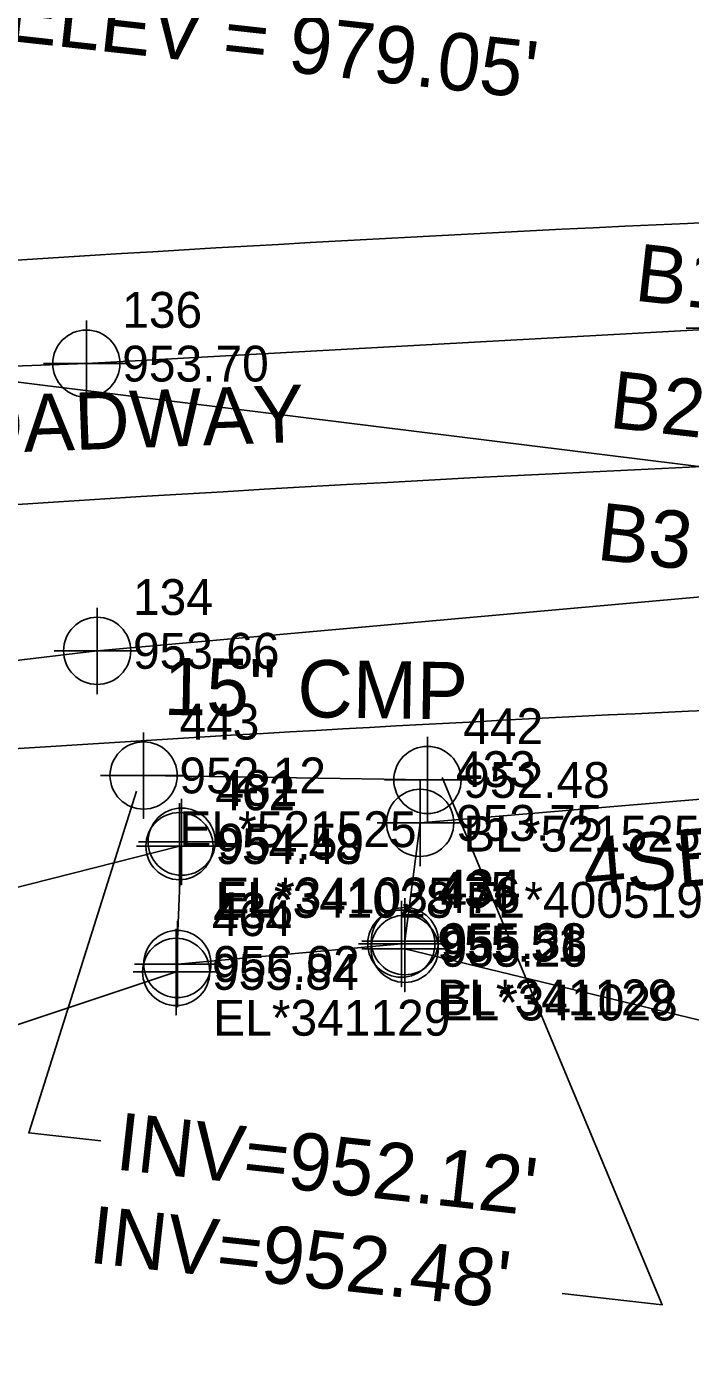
# Model space of a CAD drawing. Extents: x 1150279 to 1151282, y 655434 to 657999.
# Drawn here: x 1150667.5 to 1150713.8, y 657070.4 to 657163.6 of the extents above; entities that cross this region are included whole.
import ezdxf

# ---------------------------------------------------------------- set-up
doc = ezdxf.new("R2010")
doc.units = 0
for name, color, linetype in [('COGO Default Chain', 7, 'Continuous'), ('COGO Default Curve', 7, 'Continuous'), ('Exist Horizontal Alignment', 7, 'Continuous'), ('Exist Other Culture Fence Line', 7, 'Continuous'), ('Exist Other Culture Fence Line Cogo Comment', 7, 'Continuous'), ('Exist Other Culture Fence Line Cogo Elevation', 7, 'Continuous'), ('Exist Other Culture Fence Line Cogo Number', 7, 'Continuous'), ('Exist Other Culture Fence Line Cogo Point CELL', 7, 'Continuous'), ('Exist Other Culture Fence Line Text', 7, 'Continuous'), ('Exist Other Culture Gate', 7, 'Continuous'), ('Exist Other Culture Gate Cogo Comment', 7, 'Continuous'), ('Exist Other Culture Gate Cogo Elevation', 7, 'Continuous'), ('Exist Other Culture Gate Cogo Number', 7, 'Continuous'), ('Exist Other Culture Gate Cogo Point CELL', 7, 'Continuous'), ('Exist Other Culture Located Object Text', 7, 'Continuous'), ('Exist Right of Way Line', 7, 'Continuous'), ('Exist Roads EOP', 7, 'Continuous'), ('Exist Roads EOP Cogo Elevation', 7, 'Continuous'), ('Exist Roads EOP Cogo Number', 7, 'Continuous'), ('Exist Roads EOP Cogo Point CELL', 7, 'Continuous'), ('Exist Roads EOP Text', 7, 'Continuous'), ('Exist Structure Minor Pipes CMP 15 Inch', 7, 'Continuous'), ('Exist Structure Minor Pipes CMP 15 Inch Cogo Comment', 7, 'Continuous'), ('Exist Structure Minor Pipes CMP 15 Inch Cogo Elevation', 7, 'Continuous'), ('Exist Structure Minor Pipes CMP 15 Inch Cogo Number', 7, 'Continuous'), ('Exist Structure Minor Pipes CMP 15 Inch Cogo Point CELL', 7, 'Continuous'), ('Exist Structure Minor Pipes CMP 15 Inch Leader', 7, 'Continuous'), ('Exist Structure Minor Pipes CMP 15 Inch Text', 7, 'Continuous'), ('Exist Utilities Other Located Object Text', 7, 'Continuous')]:
    doc.layers.add(name, color=color, linetype=linetype)

msp = doc.modelspace()

# ---------------------------------------------------------------- linework, layer by layer
at = {"layer": 'COGO Default Chain'}
msp.add_line((1150614.756, 657145.261), (1150931.292, 657106.062), dxfattribs=at)
msp.add_arc((1150828.329, 654635.498), 2500, 91.662542, 95.877614, dxfattribs=at)
at = {"layer": 'COGO Default Curve'}
msp.add_arc((1150828.329, 654635.498), 2500, 91.662542, 95.877614, dxfattribs=at)
at = {"layer": 'Exist Horizontal Alignment'}
msp.add_arc((1150828.329, 654635.498), 2500, 91.662542, 95.877614, dxfattribs=at)
at = {"layer": 'Exist Other Culture Fence Line'}
for points in [[(1150742.984, 657123.479), (1150720.806, 657110.237), (1150694.904, 657108.056), (1150693.831, 657099.804)], [(1150604.364, 657025.637), (1150606.718, 657040.787), (1150614.664, 657070.42), (1150624.719, 657081.252), (1150654.476, 657089.879), (1150677.88, 657097.661), (1150678.264, 657106.743)], [(1150601.904, 657018.952), (1150605.153, 657042.825), (1150611.977, 657072.418), (1150621.899, 657082.995), (1150637.683, 657096.184), (1150678.109, 657106.438)], [(1150771.144, 656993.524), (1150752.14, 657032.017), (1150729.275, 657075.13), (1150719.487, 657093.066), (1150693.827, 657099.275)]]:
    msp.add_lwpolyline(points, dxfattribs=at)
at = {"layer": 'Exist Other Culture Fence Line Cogo Point CELL'}
for points in [[(1150694.904, 657111.056), (1150694.904, 657105.056), (1150694.904, 657108.056), (1150697.904, 657108.056), (1150691.904, 657108.056)], [(1150678.109, 657109.438), (1150678.109, 657103.438), (1150678.109, 657106.438), (1150681.109, 657106.438), (1150675.109, 657106.438)], [(1150678.264, 657109.743), (1150678.264, 657103.743), (1150678.264, 657106.743), (1150681.264, 657106.743), (1150675.264, 657106.743)], [(1150693.831, 657102.804), (1150693.831, 657096.804), (1150693.831, 657099.804), (1150696.831, 657099.804), (1150690.831, 657099.804)], [(1150693.827, 657102.275), (1150693.827, 657096.275), (1150693.827, 657099.275), (1150696.827, 657099.275), (1150690.827, 657099.275)], [(1150677.88, 657100.661), (1150677.88, 657094.661), (1150677.88, 657097.661), (1150680.88, 657097.661), (1150674.88, 657097.661)]]:
    msp.add_lwpolyline(points, dxfattribs=at)
for centre in [(1150694.904, 657108.056), (1150678.109, 657106.438), (1150678.264, 657106.743), (1150693.831, 657099.804), (1150693.827, 657099.275), (1150677.88, 657097.661)]:
    msp.add_circle(centre, 2.344, dxfattribs=at)
at = {"layer": 'Exist Other Culture Gate'}
msp.add_line((1150693.593, 657099.63), (1150677.966, 657098.213), dxfattribs=at)
at = {"layer": 'Exist Other Culture Gate Cogo Point CELL'}
for points in [[(1150693.593, 657102.63), (1150693.593, 657096.63), (1150693.593, 657099.63), (1150696.593, 657099.63), (1150690.593, 657099.63)], [(1150677.966, 657101.213), (1150677.966, 657095.213), (1150677.966, 657098.213), (1150680.966, 657098.213), (1150674.966, 657098.213)]]:
    msp.add_lwpolyline(points, dxfattribs=at)
for centre in [(1150693.593, 657099.63), (1150677.966, 657098.213)]:
    msp.add_circle(centre, 2.344, dxfattribs=at)
at = {"layer": 'Exist Right of Way Line'}
for radius, end in [(2517, 94.865015), (2483, 94.404472)]:
    msp.add_arc((1150828.329, 654635.498), radius, 91.662542, end, dxfattribs=at)
at = {"layer": 'Exist Roads EOP'}
for points in [[(1150716.457, 657142.572), (1150671.616, 657140.096), (1150622.503, 657138.316)], [(1150717.083, 657124.055), (1150672.367, 657120.059), (1150646.285, 657116.941)]]:
    msp.add_lwpolyline(points, dxfattribs=at)
at = {"layer": 'Exist Roads EOP Cogo Point CELL'}
for points in [[(1150716.457, 657145.572), (1150716.457, 657139.572), (1150716.457, 657142.572), (1150719.457, 657142.572), (1150713.457, 657142.572)], [(1150671.616, 657143.096), (1150671.616, 657137.096), (1150671.616, 657140.096), (1150674.616, 657140.096), (1150668.616, 657140.096)], [(1150672.367, 657123.059), (1150672.367, 657117.059), (1150672.367, 657120.059), (1150675.367, 657120.059), (1150669.367, 657120.059)]]:
    msp.add_lwpolyline(points, dxfattribs=at)
for centre in [(1150671.616, 657140.096), (1150672.367, 657120.059)]:
    msp.add_circle(centre, 2.344, dxfattribs=at)
at = {"layer": 'Exist Structure Minor Pipes CMP 15 Inch'}
msp.add_line((1150695.411, 657111.053), (1150675.608, 657111.366), dxfattribs=at)
at = {"layer": 'Exist Structure Minor Pipes CMP 15 Inch Cogo Point CELL'}
for points in [[(1150675.608, 657114.366), (1150675.608, 657108.366), (1150675.608, 657111.366), (1150678.608, 657111.366), (1150672.608, 657111.366)], [(1150695.411, 657114.053), (1150695.411, 657108.053), (1150695.411, 657111.053), (1150698.411, 657111.053), (1150692.411, 657111.053)]]:
    msp.add_lwpolyline(points, dxfattribs=at)
for centre in [(1150675.608, 657111.366), (1150695.411, 657111.053)]:
    msp.add_circle(centre, 2.344, dxfattribs=at)
at = {"layer": 'Exist Structure Minor Pipes CMP 15 Inch Leader'}
for points in [[(1150696.437, 657111.217), (1150711.797, 657074.444), (1150704.813, 657075.217)], [(1150675.107, 657110.278), (1150667.593, 657086.435), (1150672.616, 657085.879)]]:
    msp.add_lwpolyline(points, dxfattribs=at)

# ---------------------------------------------------------------- texts
at = {"layer": 'Exist Other Culture Fence Line Cogo Comment'}
for s, p in [('EL*341028 EL*400519', (1150680.609, 657101.438)), ('EL*341035', (1150680.764, 657101.743)), ('EL*341028', (1150696.327, 657094.275))]:
    msp.add_text(s, height=2.5, dxfattribs=at).set_placement(p)
at = {"layer": 'Exist Other Culture Fence Line Cogo Elevation'}
for s, p in [('953.75', (1150697.404, 657106.807)), ('954.48', (1150680.609, 657105.188)), ('954.59', (1150680.764, 657105.493)), ('955.38', (1150696.331, 657098.554)), ('955.26', (1150696.327, 657098.025)), ('955.84', (1150680.38, 657096.411))]:
    msp.add_text(s, height=2.5, dxfattribs=at).set_placement(p)
at = {"layer": 'Exist Other Culture Fence Line Cogo Number'}
for s, p in [('433', (1150697.404, 657110.557)), ('462', (1150680.609, 657108.938)), ('481', (1150680.764, 657109.243)), ('434', (1150696.331, 657102.304)), ('476', (1150696.327, 657101.775)), ('464', (1150680.38, 657100.161))]:
    msp.add_text(s, height=2.5, dxfattribs=at).set_placement(p)
at = {"layer": 'Exist Other Culture Fence Line Text'}
msp.add_text('4SBW', height=4, rotation=4.81184, dxfattribs=at).set_placement((1150706.414, 657103.004))
at = {"layer": 'Exist Other Culture Gate Cogo Comment'}
for s, p in [('BL*341129', (1150696.093, 657094.63)), ('EL*341129', (1150680.466, 657093.213))]:
    msp.add_text(s, height=2.5, dxfattribs=at).set_placement(p)
at = {"layer": 'Exist Other Culture Gate Cogo Elevation'}
for s, p in [('955.51', (1150696.093, 657098.38)), ('956.02', (1150680.466, 657096.963))]:
    msp.add_text(s, height=2.5, dxfattribs=at).set_placement(p)
at = {"layer": 'Exist Other Culture Gate Cogo Number'}
for s, p in [('435', (1150696.093, 657102.13)), ('436', (1150680.466, 657100.713))]:
    msp.add_text(s, height=2.5, dxfattribs=at).set_placement(p)
at = {"layer": 'Exist Other Culture Located Object Text'}
for s, p in [('B1', (1150709.784, 657144.499)), ('B2', (1150708.024, 657135.634)), ('B3', (1150707.148, 657126.428))]:
    msp.add_text(s, height=4, rotation=353.6867, dxfattribs=at).set_placement(p)
at = {"layer": 'Exist Roads EOP Cogo Elevation'}
for s, p in [('953.70', (1150674.116, 657138.846)), ('953.66', (1150674.867, 657118.809))]:
    msp.add_text(s, height=2.5, dxfattribs=at).set_placement(p)
at = {"layer": 'Exist Roads EOP Cogo Number'}
for s, p in [('136', (1150674.116, 657142.596)), ('134', (1150674.867, 657122.559))]:
    msp.add_text(s, height=2.5, dxfattribs=at).set_placement(p)
at = {"layer": 'Exist Roads EOP Text'}
msp.add_text("20' +/- PAVED ROADWAY", height=4, rotation=2.07519, dxfattribs=at).set_placement((1150623.329, 657132.342))
at = {"layer": 'Exist Structure Minor Pipes CMP 15 Inch Cogo Comment'}
for s, p in [('EL*521525', (1150678.108, 657106.366)), ('BL*521525', (1150697.911, 657106.053))]:
    msp.add_text(s, height=2.5, dxfattribs=at).set_placement(p)
at = {"layer": 'Exist Structure Minor Pipes CMP 15 Inch Cogo Elevation'}
for s, p in [('952.12', (1150678.108, 657110.116)), ('952.48', (1150697.911, 657109.803))]:
    msp.add_text(s, height=2.5, dxfattribs=at).set_placement(p)
at = {"layer": 'Exist Structure Minor Pipes CMP 15 Inch Cogo Number'}
for s, p in [('443', (1150678.108, 657113.866)), ('442', (1150697.911, 657113.553))]:
    msp.add_text(s, height=2.5, dxfattribs=at).set_placement(p)
at = {"layer": 'Exist Structure Minor Pipes CMP 15 Inch Text'}
for s, rotation, p in [('15" CMP', 359.09532, (1150676.981, 657115.591)), ("INV=952.12'", 353.6867, (1150673.566, 657083.892)), ("INV=952.48'", 353.6867, (1150671.706, 657077.389))]:
    msp.add_text(s, height=4, rotation=rotation, dxfattribs=at).set_placement(p)
at = {"layer": 'Exist Utilities Other Located Object Text'}
msp.add_text("ELEV = 979.05'", height=4, rotation=353.6867, dxfattribs=at).set_placement((1150665.933, 657162.641))

doc.saveas('drawing.dxf')
